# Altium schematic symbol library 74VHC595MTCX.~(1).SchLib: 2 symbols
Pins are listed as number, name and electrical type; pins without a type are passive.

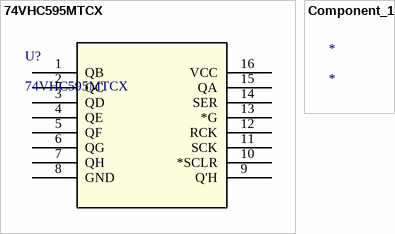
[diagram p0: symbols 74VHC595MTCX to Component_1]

## 74VHC595MTCX
designator U?
No Description Available; Mfr_Name: onsemi
footprint TSSOP16_5X4P5_ONS
pins: 1 QB, 2 QC, 3 QD, 4 QE, 5 QF, 6 QG, 7 QH, 8 GND, 9 Q'H, 10 *SCLR, 11 SCK, 12 RCK, 13 *G, 14 SER, 15 QA, 16 VCC (power)

## Component_1
designator *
